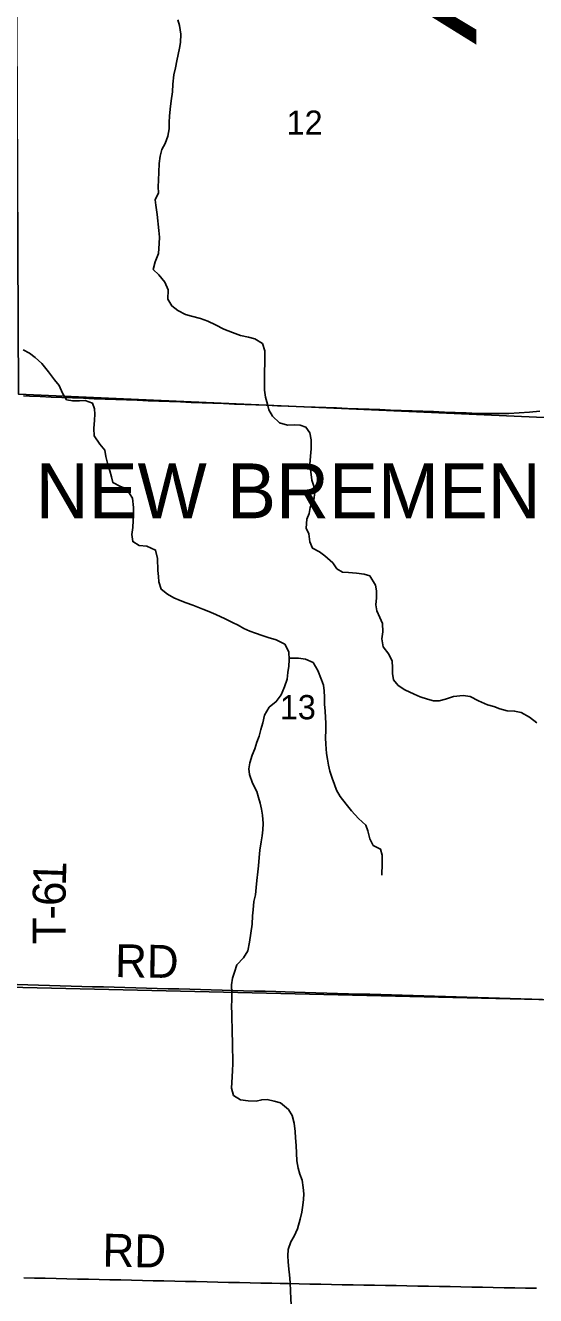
# Model space of a CAD drawing. Extents: x -11.1 to 34, y -3.9 to 22.
# Drawn here: x 6.389 to 7.271, y 14.712 to 16.906 of the extents above; entities that cross this region are included whole.
import ezdxf

# ---------------------------------------------------------------- set-up
doc = ezdxf.new("R2010")
doc.units = 0
for name, color, linetype in [('GM_X_Corporation', 7, 'Continuous'), ('GM_X_Corporation_Text', 7, 'Continuous'), ('GM_X_County_Road', 7, 'Continuous'), ('GM_X_County_Road_Text', 7, 'Continuous'), ('GM_X_County_Text', 7, 'Continuous'), ('GM_X_Minor_River', 7, 'Continuous'), ('GM_X_Section_Text', 7, 'Continuous'), ('GM_X_State_Route', 7, 'Continuous'), ('GM_X_Township_Road_Text', 7, 'Continuous')]:
    doc.layers.add(name, color=color, linetype=linetype)

msp = doc.modelspace()

# ---------------------------------------------------------------- linework, layer by layer
at = {"layer": 'GM_X_Corporation'}
for points in [[(2.1, 18.3243), (2.1, 15.3106), (2.171, 15.3082), (2.3479, 15.3077), (2.7781, 15.2969), (3.0179, 15.2909), (3.2754, 15.2855), (3.2832, 15.2853), (3.3566, 15.2846), (3.8581, 15.2731), (4.4622, 15.2602), (4.4824, 15.2598), (4.6334, 15.2569), (4.6407, 15.2568), (4.6535, 15.2566), (4.8684, 15.2535), (5.0169, 15.252), (5.2769, 15.2522), (6.3599, 15.2448), (7.3508, 15.2219)], [(7.3508, 15.2219), (6.3599, 15.2448), (5.2769, 15.2522), (5.0169, 15.252), (4.8684, 15.2535), (4.6535, 15.2566), (4.6407, 15.2568), (4.6334, 15.2569), (4.4824, 15.2598), (4.4622, 15.2602), (3.8581, 15.2731), (3.3566, 15.2846), (3.2832, 15.2853), (3.2754, 15.2855), (3.0179, 15.2909), (2.7781, 15.2969), (2.3479, 15.3077), (2.171, 15.3082), (2.1, 15.3106), (2.1, 14.1), (7.332, 14.1)]]:
    msp.add_lwpolyline(points, dxfattribs=at)
msp.add_lwpolyline([(7.3791, 17.2313), (7.364, 16.2758), (7.3634, 16.2255), (6.3775, 16.2691), (6.3727, 17.2765)], close=True, dxfattribs=at)
at = {"layer": 'GM_X_County_Road'}
for points in [[(6.375, 15.2494), (6.3936, 15.2489), (6.4123, 15.2484), (6.4309, 15.2479), (6.4496, 15.2474), (6.4682, 15.2469), (6.4868, 15.2464), (6.5055, 15.2459), (6.5241, 15.2454), (6.5427, 15.2449), (6.5614, 15.2444), (6.58, 15.2439), (6.5986, 15.2434), (6.6173, 15.2429), (6.6359, 15.2424), (6.6545, 15.2419), (6.6732, 15.2414), (6.6918, 15.2409), (6.7104, 15.2404), (6.7291, 15.2399), (6.7477, 15.2394), (6.7663, 15.2389), (6.785, 15.2384), (6.8036, 15.2379), (6.8222, 15.2374), (6.8382, 15.237), (6.8541, 15.2365), (6.8727, 15.236), (6.8914, 15.2354), (6.91, 15.2349), (6.9286, 15.2343), (6.9473, 15.2338), (6.9659, 15.2332), (6.9845, 15.2327), (7.0032, 15.2321), (7.0218, 15.2316), (7.0404, 15.231), (7.0591, 15.2304), (7.0777, 15.2299), (7.0964, 15.2293), (7.115, 15.2288), (7.1336, 15.2282), (7.1523, 15.2277), (7.1709, 15.2271), (7.1895, 15.2266), (7.2082, 15.226), (7.2268, 15.2255), (7.2454, 15.2249), (7.2641, 15.2244), (7.2827, 15.2238)], [(6.3864, 14.7431), (6.405, 14.7427), (6.4236, 14.7423), (6.4423, 14.7419), (6.4609, 14.7414), (6.4796, 14.741), (6.4982, 14.7406), (6.5168, 14.7402), (6.5355, 14.7398), (6.5541, 14.7394), (6.5727, 14.739), (6.5914, 14.7386), (6.61, 14.7381), (6.6286, 14.7377), (6.6473, 14.7373), (6.6659, 14.7369), (6.6845, 14.7365), (6.7032, 14.7361), (6.7218, 14.7357), (6.7404, 14.7352), (6.7591, 14.7348), (6.7777, 14.7344), (6.7963, 14.734), (6.815, 14.7336), (6.8293, 14.7333), (6.8437, 14.733), (6.8623, 14.7326), (6.8809, 14.7323), (6.8996, 14.7319), (6.9182, 14.7316), (6.9368, 14.7312), (6.9555, 14.7309), (6.9741, 14.7305), (6.9927, 14.7302), (7.0114, 14.7298), (7.03, 14.7295), (7.0486, 14.7291), (7.0673, 14.7288), (7.0859, 14.7284), (7.1046, 14.7281), (7.1232, 14.7278), (7.1418, 14.7274), (7.1605, 14.7271), (7.1791, 14.7267), (7.1977, 14.7264), (7.2164, 14.726), (7.235, 14.7257), (7.2536, 14.7253), (7.2723, 14.725)]]:
    msp.add_lwpolyline(points, dxfattribs=at)
at = {"layer": 'GM_X_Minor_River'}
for points in [[(6.653, 16.9157), (6.6558, 16.9061), (6.658, 16.8908), (6.6573, 16.8768), (6.6555, 16.8666), (6.6533, 16.856), (6.6512, 16.8447), (6.6486, 16.8329), (6.646, 16.8208), (6.6441, 16.8049), (6.6437, 16.7913), (6.6414, 16.7761), (6.6392, 16.7617), (6.6381, 16.7496), (6.6378, 16.739), (6.6379, 16.7276), (6.6353, 16.7147), (6.6308, 16.7019), (6.6252, 16.6918), (6.6223, 16.6805), (6.6204, 16.6676), (6.62, 16.6524), (6.6193, 16.6391), (6.619, 16.6273), (6.6191, 16.6171), (6.6135, 16.6051), (6.6148, 16.5955), (6.617, 16.5795), (6.6201, 16.5521), (6.621, 16.5406), (6.6207, 16.5292), (6.6191, 16.5122), (6.6138, 16.4979), (6.6104, 16.4846), (6.62, 16.4753), (6.63, 16.4625), (6.6361, 16.4494), (6.6353, 16.4334), (6.6422, 16.4215), (6.653, 16.4136), (6.6661, 16.4071), (6.6766, 16.4038), (6.6917, 16.4), (6.7045, 16.3955), (6.718, 16.3887), (6.7322, 16.3815), (6.7469, 16.3758), (6.7612, 16.3708), (6.7747, 16.3674), (6.7857, 16.3649), (6.7991, 16.3565), (6.803, 16.3443), (6.803, 16.3302), (6.8022, 16.301), (6.8023, 16.2873), (6.8024, 16.2762), (6.804, 16.264), (6.8074, 16.2518), (6.8102, 16.2422), (6.816, 16.2314), (6.8286, 16.2197), (6.8422, 16.2159), (6.8543, 16.2163), (6.8642, 16.2157), (6.874, 16.2124), (6.8809, 16.2027), (6.8829, 16.1901), (6.8829, 16.1749), (6.8818, 16.162), (6.881, 16.1476), (6.8829, 16.1304), (6.8845, 16.1205), (6.8877, 16.1105), (6.8893, 16.0995), (6.8874, 16.087), (6.8814, 16.0734), (6.8796, 16.0632), (6.8756, 16.0534), (6.8744, 16.0379), (6.8791, 16.0279), (6.881, 16.0142), (6.8853, 16.003), (6.8973, 15.997), (6.9069, 15.9899), (6.9203, 15.9778), (6.9276, 15.9673), (6.9373, 15.9617), (6.9476, 15.9615), (6.9616, 15.96), (6.9744, 15.9581), (6.9842, 15.9556), (6.9944, 15.9394), (6.9957, 15.9298), (6.9958, 15.9177)], [(6.3853, 16.3457), (6.3962, 16.34), (6.4062, 16.3326), (6.4177, 16.322), (6.4291, 16.3076), (6.4398, 16.294), (6.4475, 16.2843), (6.4532, 16.2709), (6.4605, 16.2597), (6.4711, 16.2575), (6.4828, 16.2579), (6.4927, 16.2584), (6.5055, 16.2535), (6.5087, 16.244), (6.5092, 16.2344), (6.5085, 16.2242), (6.5078, 16.2101), (6.5082, 16.1972), (6.5177, 16.1829), (6.5266, 16.1724), (6.5286, 16.1613), (6.5313, 16.1502), (6.5351, 16.1368), (6.5379, 16.1265), (6.5407, 16.1165), (6.5538, 16.1097), (6.5639, 16.106), (6.5745, 16.0898), (6.576, 16.0734), (6.5761, 16.0624), (6.5758, 16.0513), (6.5751, 16.0392), (6.5733, 16.0267), (6.5749, 16.0145), (6.5857, 16.0081), (6.5993, 16.0066), (6.6143, 15.9998), (6.6174, 15.9853), (6.6184, 15.9647), (6.6192, 15.9544), (6.6201, 15.9449), (6.624, 15.9322), (6.6348, 15.924), (6.646, 15.9176), (6.6565, 15.9128), (6.667, 15.9091), (6.6787, 15.905), (6.6959, 15.8981), (6.7065, 15.8936), (6.7185, 15.8887), (6.7346, 15.8811), (6.7469, 15.8751), (6.7567, 15.8703), (6.7668, 15.8647), (6.7769, 15.8599)], [(6.9958, 15.9177), (6.9947, 15.9055), (6.9963, 15.8948), (7.0017, 15.8837), (7.0064, 15.8729), (7.0068, 15.8588), (7.0049, 15.8467), (7.0076, 15.8326), (7.0171, 15.8202), (7.0229, 15.8079), (7.0234, 15.7972), (7.0235, 15.7866), (7.0255, 15.7759), (7.0336, 15.7662), (7.0448, 15.7583), (7.0609, 15.751), (7.0714, 15.7466), (7.0842, 15.7424), (7.0944, 15.7395), (7.1042, 15.7393), (7.1153, 15.7424), (7.1287, 15.747), (7.1454, 15.7488), (7.1579, 15.747), (7.1721, 15.7394), (7.1875, 15.7329), (7.1984, 15.7296), (7.2089, 15.7255), (7.2218, 15.7225), (7.2346, 15.7218), (7.246, 15.7196), (7.2602, 15.7113), (7.2732, 15.7015)], [(6.7769, 15.8599), (6.7871, 15.8562), (6.7987, 15.8524), (6.8089, 15.8491), (6.8224, 15.845), (6.8374, 15.8374), (6.8446, 15.8243), (6.845, 15.8102), (6.8444, 15.7996), (6.843, 15.7886), (6.8415, 15.7772), (6.837, 15.7637), (6.831, 15.7497), (6.8227, 15.7382), (6.8107, 15.7286), (6.8024, 15.7148), (6.7994, 15.7015), (6.796, 15.6898), (6.7931, 15.6785), (6.7894, 15.668), (6.7857, 15.6567), (6.7813, 15.6458), (6.7771, 15.6326), (6.7753, 15.6224), (6.7766, 15.6121), (6.7819, 15.5971), (6.7891, 15.5832), (6.7923, 15.5729), (6.795, 15.5629), (6.7974, 15.5526), (6.799, 15.5419), (6.8002, 15.5275), (6.7995, 15.5169), (6.7985, 15.5066), (6.7967, 15.496), (6.7944, 15.4816), (6.7934, 15.4691), (6.7922, 15.4547), (6.7908, 15.4445), (6.7893, 15.4294), (6.7878, 15.4169), (6.7868, 15.4047), (6.7842, 15.393), (6.7827, 15.3786), (6.782, 15.3684), (6.7809, 15.3536), (6.7767, 15.3229), (6.7736, 15.3078), (6.7661, 15.2959), (6.7548, 15.2836), (6.7506, 15.2708), (6.7473, 15.2603), (6.7455, 15.2489), (6.7459, 15.2348), (6.746, 15.2234), (6.7457, 15.2117), (6.7458, 15.1995), (6.7458, 15.1885), (6.7467, 15.176), (6.7468, 15.1653), (6.7472, 15.152), (6.7471, 15.1368), (6.7476, 15.1243), (6.7477, 15.1129), (6.7474, 15.1011), (6.7467, 15.0901), (6.7461, 15.0806), (6.7454, 15.0708), (6.7489, 15.0582), (6.7608, 15.0503), (6.7741, 15.0488), (6.7881, 15.0484), (6.7976, 15.0505), (6.8071, 15.051), (6.8192, 15.0484), (6.8301, 15.0451), (6.8438, 15.0337), (6.85, 15.0233), (6.8538, 15.0103), (6.8554, 14.9958), (6.8558, 14.9848), (6.8574, 14.9714), (6.8578, 14.9585), (6.8586, 14.9452), (6.8609, 14.9322), (6.8637, 14.9219), (6.8676, 14.9116), (6.8691, 14.899), (6.8704, 14.8883), (6.8701, 14.8785), (6.8687, 14.8686), (6.8669, 14.8565), (6.8643, 14.8444), (6.8597, 14.8279), (6.8536, 14.8151), (6.8477, 14.8054), (6.8436, 14.7922), (6.8429, 14.7808), (6.8434, 14.7706), (6.8446, 14.758), (6.8454, 14.7481)], [(6.845, 15.8134), (6.8611, 15.8132), (6.8735, 15.8117), (6.8863, 15.8057), (6.8947, 15.7922), (6.9011, 15.7761), (6.9042, 15.7665), (6.9055, 15.7569), (6.906, 15.7459), (6.9064, 15.7341), (6.9073, 15.7219), (6.9077, 15.7109), (6.9082, 15.701), (6.9083, 15.6888), (6.908, 15.6759), (6.9084, 15.6649), (6.9095, 15.6485), (6.9112, 15.639), (6.9132, 15.6283), (6.9156, 15.6183), (6.9191, 15.6061), (6.9233, 15.5953), (6.9269, 15.5854), (6.9334, 15.5746), (6.9433, 15.561), (6.9529, 15.5494), (6.9651, 15.5365), (6.9773, 15.5248), (6.9812, 15.5148), (6.9843, 15.5014), (6.9904, 15.4899), (7.0028, 15.4835), (7.0055, 15.4732), (7.0059, 15.4587), (7.0054, 15.4382)], [(6.8454, 14.7481), (6.847, 14.7348), (6.8474, 14.72), (6.8478, 14.7074), (6.8486, 14.6964), (6.849, 14.6816), (6.8485, 14.6615), (6.8477, 14.6486), (6.8471, 14.6368), (6.846, 14.6259), (6.8441, 14.6119), (6.8431, 14.6013), (6.8416, 14.5876), (6.8405, 14.5755), (6.841, 14.566)]]:
    msp.add_lwpolyline(points, dxfattribs=at)
at = {"layer": 'GM_X_State_Route'}
msp.add_lwpolyline([(6.386, 16.2661), (6.3964, 16.2657), (6.4151, 16.265), (6.4337, 16.2643), (6.4523, 16.2636), (6.471, 16.2629), (6.4896, 16.2622), (6.5082, 16.2614), (6.5269, 16.2607), (6.5455, 16.26), (6.5641, 16.2593), (6.5827, 16.2586), (6.6014, 16.2579), (6.62, 16.2572), (6.6386, 16.2564), (6.6573, 16.2557), (6.6759, 16.255), (6.6945, 16.2543), (6.7131, 16.2536), (6.7318, 16.2529), (6.7504, 16.2522), (6.769, 16.2515), (6.7877, 16.2507), (6.8063, 16.25), (6.8249, 16.2493), (6.8435, 16.2486), (6.8574, 16.2481), (6.8712, 16.2476), (6.8898, 16.2468), (6.9084, 16.2461), (6.9271, 16.2454), (6.9457, 16.2447), (6.9643, 16.244), (6.983, 16.2433), (7.0016, 16.2426), (7.0202, 16.2418), (7.0388, 16.2411), (7.0575, 16.2404), (7.0761, 16.2397), (7.0947, 16.239), (7.1134, 16.2383), (7.132, 16.2376), (7.1506, 16.2369), (7.1609, 16.2365), (7.1712, 16.2361), (7.189, 16.2356), (7.2069, 16.2358), (7.2248, 16.236), (7.2427, 16.2369), (7.2605, 16.2382), (7.2783, 16.2399)], dxfattribs=at)

# ---------------------------------------------------------------- texts
at = {"layer": 'GM_X_Corporation_Text'}
msp.add_text('NEW BREMEN', height=0.0947, rotation=0, dxfattribs=at).set_placement((6.4073, 16.0549))
at = {"layer": 'GM_X_County_Road_Text'}
for rotation, p in [(359.0118, (6.5439, 15.2625)), (359.0128, (6.5222, 14.7625))]:
    msp.add_text('RD', height=0.05682, rotation=rotation, dxfattribs=at).set_placement(p)
at = {"layer": 'GM_X_County_Text'}
msp.add_text('Y', height=0.1894, rotation=269.4063, dxfattribs=at).set_placement((6.9806, 17.0382))
at = {"layer": 'GM_X_Section_Text'}
for s, p in [('12', (6.8406, 16.7172)), ('13', (6.8289, 15.7077))]:
    msp.add_text(s, height=0.04186, rotation=0, dxfattribs=at).set_placement(p)
at = {"layer": 'GM_X_Township_Road_Text'}
for s, rotation, p in [('1', 88.1288, (6.4591, 15.4197)), ('6', 89.6253, (6.4588, 15.3851)), ('-', 89.9219, (6.4588, 15.3618)), ('T', 89.9936, (6.4588, 15.3193))]:
    msp.add_text(s, height=0.0568, rotation=rotation, dxfattribs=at).set_placement(p)

doc.saveas('drawing.dxf')
